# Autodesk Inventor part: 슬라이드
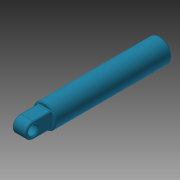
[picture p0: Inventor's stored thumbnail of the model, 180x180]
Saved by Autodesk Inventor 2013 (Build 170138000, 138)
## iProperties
Created: 2016-02
Part Number: 슬라이드
Material: 강철, 연강
Document SubType Name: Modeling
Designer: test
Density: 1 g/cm^3
Author: test
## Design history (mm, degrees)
sketch "스케치2"
  geometry: C1 r 6 at (0, 0); 1 further point
  constraints: 1 centre point, 1 coincident
  dimensions: "d0" = 12 diameter of C1
extrude "돌출1" new body sketch "스케치2" distance "d1" = 60; taper "d2" = 0 deg
hole "구멍1" diameter "d5" = 5.917; stored, may be unused: countersink angle "d9" = 90 deg, drill point angle "d11" = 118 deg; dims "d3" = 10, "d4" = 10, "d6" = 10, "d7" = 4, "d8" = 2, "d10" = 12
chamfer "모따기1" distance "d12" = 1; stored, may be unused: second distance "d13" = 2, angle "d14" = 45 deg
sketch "스케치3"
  geometry: L1 (0, 6)-(0, -6) reference; L2 (0, 4)-(-9, 4); L3 (-9, -4)-(0, -4); L4 (0, -4)-(0, 4); C1 r 2.5 at (-9, 0); A1 r 4 centre (-9, 0) between (-9, 4) and (-9, -4); 2 further points
  constraints: 6 end point, 2 centre point, 2 point on circle, 2 tangent, 1 coincident, 1 horizontal, 1 horizontal alignment, 1 midpoint, 1 parallel, 1 point on line, 1 vertical
  dimensions: "d15" = 13 dimension on A1 L1; "d16" = 8 distance between parallel lines of L3 L2; "d17" = 5 diameter of C1
extrude "돌출2" join sketch "스케치3" stored distance "d18" = 7; taper "d19" = 0 deg
chamfer "모따기2" distance "d20" = 0.5; stored, may be unused: second distance "d21" = 2, angle "d22" = 45 deg
fillet "모깎기1" dims "d23" = 0.5
fillet "모깎기2" dims "d24" = 0.5
fillet "모깎기3" dims "d25" = 0.5
node "솔리드1"
